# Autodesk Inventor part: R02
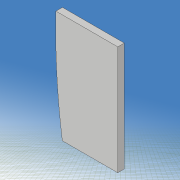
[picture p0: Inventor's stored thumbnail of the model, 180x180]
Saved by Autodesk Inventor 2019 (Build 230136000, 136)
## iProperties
Created: 2021-05
Part Number: R02
Material: 一般
Document SubType Name: Modeling
Designer: kikut
Density: 1 g/cm^3
Appearance: 既定
Mass: 0.131458 g
Surface Area: 4.7357 cm^2
Volume: 0.131458 cm^3
Author: kikut
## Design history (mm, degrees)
sketch "スケッチ1"
  geometry: L1 (80, 60)-(-80, 60); L2 (-80, 60)-(-80, -60); L3 (-80, -60)-(80, -60); L4 (80, -60)-(80, 60); L5 (80, 60)-(-80, -60); L6 (-80, 60)-(80, -60); 1 further point
  constraints: 12 end point, 2 midpoint, 2 parallel, 1 horizontal, 1 perpendicular
  dimensions: "d0" = 160 distance of L2.end L3.end; "d1" = 120 distance of L1.end L2.end
extrude "押し出し1" new body sketch "スケッチ1" stored distance "d2" = 0.6; taper "d3" = 0 deg
sketch "スケッチ2"
  geometry: L1 (-140, 0)-(140, 0) reference; L2 (0, -54)-(20, -30); L3 (0, 54)-(20, 30); L4 (0, -3)-(6.514, -3); L5 (6.514, -3)-(16, -6); L6 (16, -6)-(24, -3); L7 (24, -3)-(33.716, -3); L8 (0, 3)-(6.514, 3); L9 (6.514, 3)-(16, 6); L10 (16, 6)-(24, 3); L11 (24, 3)-(33.716, 3); L12 (0, -98)-(0, 98) reference; L13 (-100, -70)-(100, -70); L14 (100, -70)-(100, 70); L15 (100, 70)-(-100, 70); L16 (-100, 70)-(-100, -70); L17 (-100, -70)-(100, 70); L18 (100, -70)-(-100, 70); A1 r 60 centre (54.312, 28.5) between (0, 54) and (0, 3); A2 r 60 centre (54.312, -28.5) between (0, -3) and (0, -54); A3 r 18.111 centre (18, -12) between (20, -30) and (33.716, -3); A4 r 18.111 centre (18, 12) between (33.716, 3) and (20, 30); 1 further point
  constraints: 32 end point, 8 point on circle, 8 symmetric about line, 4 centre point, 3 horizontal, 2 collinear, 2 midpoint, 2 parallel, 1 perpendicular
  dimensions: "d5" = 60 radius of A1; "d6" = 6 distance of L8.start L4.start; "d7" = 108 distance of L3.start L2.start; "d8" = 0 horizontal distance of L3.start L8.start; "d9" = 60 distance of L3.end L2.end; "d10" = 0 horizontal distance of point (0, 0) L3.start; "d11" = 20 horizontal distance of L3.start L3.end; "d12" = 24 distance of A4.centre A3.centre; "d13" = 6 distance of L11.end L7.end; "d14" = 12 distance of L9.end L5.end; "d15" = 16 distance from line of L12 L5.end; "d16" = 24 distance from line of L6.end L12; "d17" = 200 distance of L14.end L15.end; "d18" = 140 distance of L15.end L13.start; "d30" = 18 distance from line of L12 A4.centre
extrude "押し出し2" cut sketch "スケッチ2" stored distance "d19" = 10; taper "d20" = 0 deg
sketch "スケッチ3"
  geometry: L1 (49.705, -17.97)-(33.948, -15.191); L2 (33.948, -15.191)-(34.295, -13.222); L3 (34.295, -13.222)-(50.052, -16); L4 (50.052, -16)-(49.705, -17.97); L5 (49.705, -17.97)-(34.295, -13.222); L6 (33.948, -15.191)-(50.052, -16); L7 (50.052, 16)-(34.295, 13.222); L8 (34.295, 13.222)-(33.948, 15.191); L9 (33.948, 15.191)-(49.705, 17.97); L10 (49.705, 17.97)-(50.052, 16); L11 (50.052, 16)-(33.948, 15.191); L12 (34.295, 13.222)-(49.705, 17.97); L13 (-112, 0)-(112, 0) reference; L14 (0, -84)-(0, 84) reference; 3 further points
  constraints: 24 end point, 4 midpoint, 4 parallel, 2 perpendicular, 2 symmetric about line
  dimensions: "d21" = 2 distance of L3.end L1.start; "d22" = 2 distance of L9.end L7.start; "d23" = 16 distance of L8.end L9.end; "d24" = 42 distance from line of L14 point (42, 15.596); "d26" = 10 deg angle of L7 L13; "d62" = 16 distance from line of L3.end L13
extrude "押し出し3" join sketch "スケッチ3" distance "d27" = 0.6; taper "d28" = 0 deg
fillet "フィレット1" dims "d31" = 2
fillet "フィレット2" dims "d32" = 1
sketch "スケッチ6"
  geometry: L1 (-20, 60)-(80, 60); L2 (80, 60)-(80, -60); L3 (80, -60)-(-20, -60); L4 (-20, -60)-(-20, 60); L5 (-46.168, 0)-(93.832, 0) reference; L6 (0, -84)-(0, 84) reference; L7 (-10, 20)-(0, 20); L8 (0, 20)-(0, 30); L9 (0, 30)-(-10, 30); L10 (-10, 30)-(-10, 20); 1 further point
  constraints: 16 end point, 4 parallel, 2 horizontal, 2 perpendicular, 1 other
  dimensions: "d63" = 120 distance of L3.end L1.start; "d64" = 100 distance of L1.start L1.end; "d65" = 20 distance between parallel lines of L6 L4; "d66" = 10 distance of L8.end L9.end; "d69" = 10 distance between parallel lines of L6 L10; "d72" = 30 distance between parallel lines of L1 L9; "d73" = 10 distance of L9.end L7.start
extrude "押し出し4" cut sketch "スケッチ6" stored distance "d70" = 10; taper "d71" = 0 deg
node "ソリッド1"
